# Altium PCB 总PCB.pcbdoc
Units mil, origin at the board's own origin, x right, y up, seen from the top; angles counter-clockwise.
Board outline 1771.65 x 3543.31 mil, 2 copper layers (Top Layer, Bottom Layer), stack 62.205 mil thick; 113 components, 79 nets, 415 pads, 177 vias.
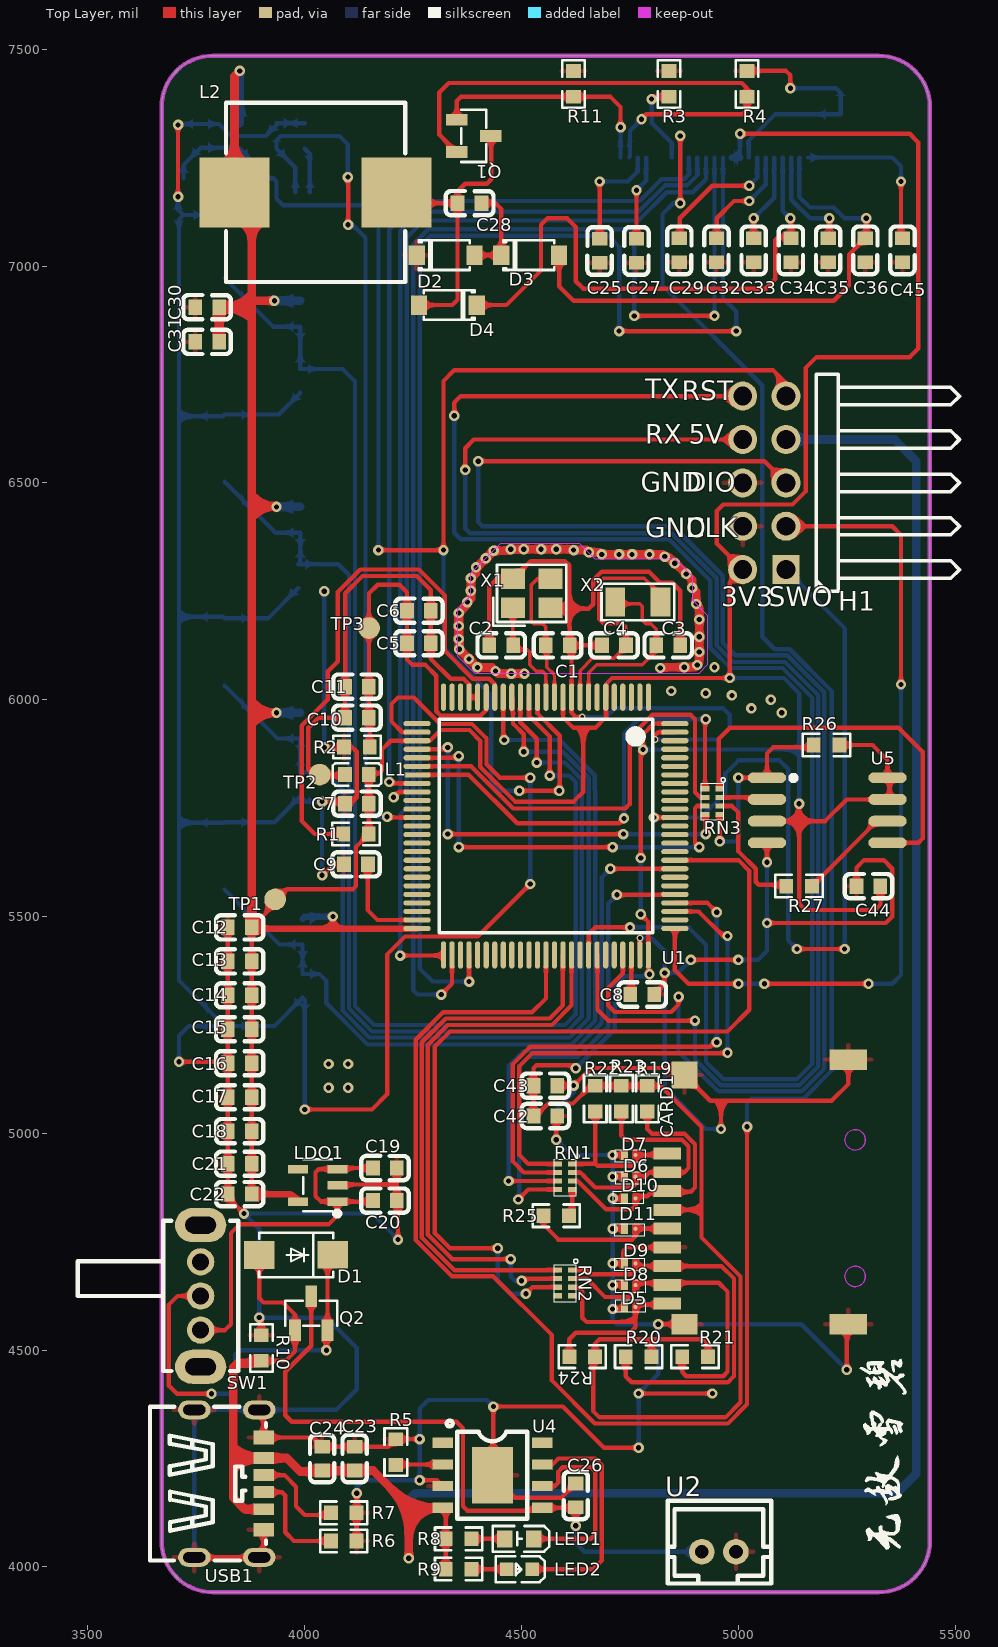
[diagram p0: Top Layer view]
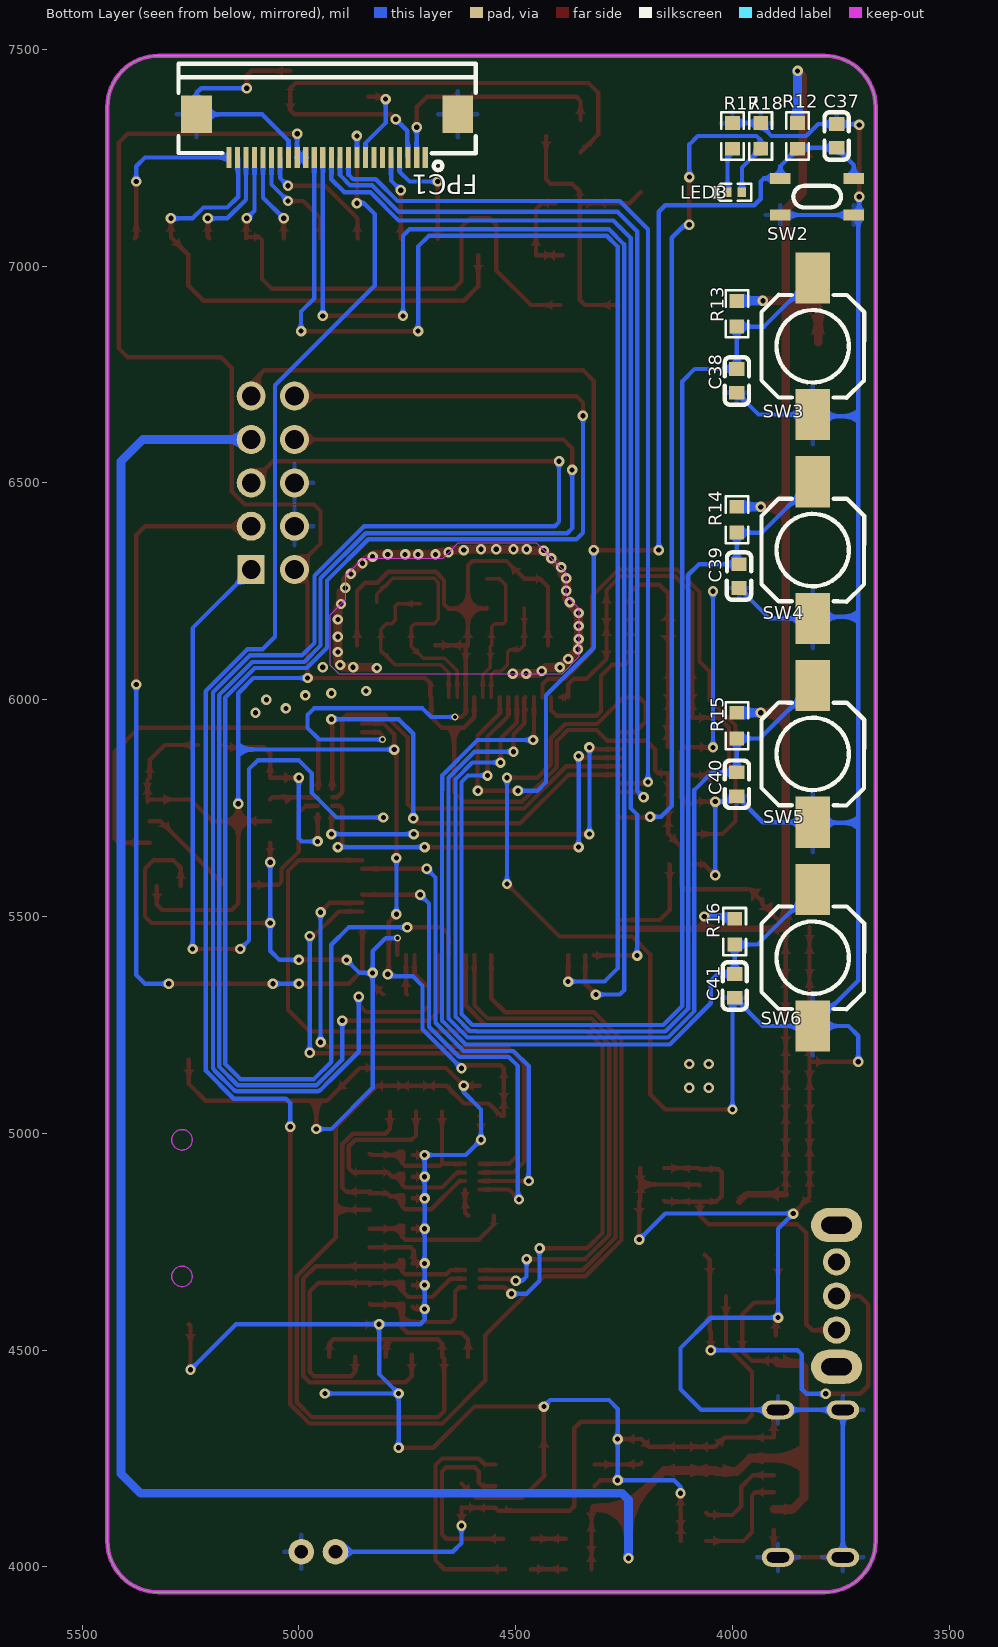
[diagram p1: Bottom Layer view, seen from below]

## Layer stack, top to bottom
Top Solder Mask Layer: solder mask 0.394, Dk 3.3
Top Layer: signal copper 1.378
Dielectric1: surface 59.449, FR4, Dk 4.5
Bottom Layer: signal copper 1.378
Bottom Solder Mask Layer: solder mask 0.394, Dk 3.3

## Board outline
3788.11,7485 5323.54,7485 cw(c5323.54,7366.89) 5441.65,7366.89 5441.65,4059.8 cw(c5323.54,4059.8) 5323.54,3941.69 3788.11,3941.69 cw(c3788.11,4059.8) 3670,4059.8 3670,7366.89 cw(c3788.11,7366.89)

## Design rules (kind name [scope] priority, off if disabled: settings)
BoardOutlineClearance copperThickness1oz [All] p0: genericclearance=10 ignorepadtopadclearanceinfootprint=FALSE except(0: Arc-SplitContinuation Track-SplitContinuation SMDPad-SplitContinuation THPad-SplitContinuation Via-SplitContinuation Fill-SplitContinuation Poly-SplitContinuation Region-SplitContinuation Text-SplitContinuation)
BoardOutlineClearance copperThickness2oz [All] p0: genericclearance=10 ignorepadtopadclearanceinfootprint=FALSE except(0: Arc-SplitContinuation Track-SplitContinuation SMDPad-SplitContinuation THPad-SplitContinuation Via-SplitContinuation Fill-SplitContinuation Poly-SplitContinuation Region-SplitContinuation Text-SplitContinuation)
BoardOutlineClearance copperThicknessInner0.5oz [All] p0: genericclearance=10 ignorepadtopadclearanceinfootprint=FALSE except(0: Arc-SplitContinuation Track-SplitContinuation SMDPad-SplitContinuation THPad-SplitContinuation Via-SplitContinuation Fill-SplitContinuation Poly-SplitContinuation Region-SplitContinuation Text-SplitContinuation)
BoardOutlineClearance otherClearance [All] p0: genericclearance=10 ignorepadtopadclearanceinfootprint=FALSE except(0: Arc-SplitContinuation Track-SplitContinuation SMDPad-SplitContinuation THPad-SplitContinuation Via-SplitContinuation Fill-SplitContinuation Poly-SplitContinuation Region-SplitContinuation Text-SplitContinuation)
Clearance copperThickness1oz [All] p1: gap=7 ignorepadtopadclearanceinfootprint=FALSE
Clearance copperThickness2oz [All] p1: gap=7 ignorepadtopadclearanceinfootprint=FALSE
Clearance copperThicknessInner0.5oz [All] p1: gap=7 ignorepadtopadclearanceinfootprint=FALSE
Clearance otherClearance [All] p1: gap=7 ignorepadtopadclearanceinfootprint=FALSE
DiffPairsRouting differentialPair [All] p1: maxuncoupledlength=10 minlimit=5.9843 maxlimit=Infinity mostfreqgap=5.9843 toplayer_minwidth=5 toplayer_prefwidth=10 toplayer_maxwidth=100 bottomlayer_minwidth=5 bottomlayer_prefwidth=10 bottomlayer_maxwidth=100
PasteMaskExpansion pasteMaskExpansion [All] p1: expansion=0
PlaneConnect innerPlane [All] p1: planeconnectstyle=Relief reliefexpansion=20 reliefentries=4 reliefconductorwidth=10 reliefairgap=10
PolygonConnect copperRegion [All] p1: connectstyle=Relief reliefentries=4 reliefconductorwidth=10 polygonreliefangle="90 Angle" airgapwidth=10
RoutingVias viaSize [All] p1: viastyle="Through Hole" holewidth=12.0078 minholewidth=7.874 maxholewidth=248.0314 width=12.0078 minwidth=7.874 maxwidth=248.0314
SolderMaskExpansion solderMaskExpansion [IsVia] p1: useseparateexpansions=TRUE expansion=-1000 expansionbottom=-1000
SolderMaskExpansion solderMaskExpansion [All] p2: useseparateexpansions=TRUE expansion=2.0079 expansionbottom=2.0079
Width copperThickness1oz [All] p1: maxlimit=100 minlimit=4 preferedwidth=10
Width copperThickness2oz [All] p1: maxlimit=100 minlimit=8 preferedwidth=10
Width copperThickness0.5oz [All] p1: maxlimit=100 minlimit=4 preferedwidth=10

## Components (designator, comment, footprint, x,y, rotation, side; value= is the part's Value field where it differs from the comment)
C1 "20pF" C0603#1 4583.25,6125.21 r180 top
C2 "20pF" C0603#1 4453.25,6125.21 r0 top
C3 "12pF" C0603#1 4838.25,6125.21 r180 top
C4 "12pF" C0603#1 4713.25,6125.21 r0 top
C5 "1uF" C0603#1 4263.25,6130.21 r0 top
C6 "100nF" C0603#1 4263.25,6205.21 r180 top
C7 "100nF" C0603#1 4120.44,5760.21 r180 top
C8 "2.2uF" C0603#1 4778.25,5320.21 r180 top
C9 "2.2uF" C0603#1 4118.25,5620.21 r0 top
C10 "1uF" C0603#1 4120.44,5958.57 r0 top
C11 "100nF" C0603#1 4120.44,6030.21 r180 top
C12 "10uF" C0603#1 3850,5475 r0 top
C13 "100nF" C0603#1 3850,5396.67 r0 top
C14 "100nF" C0603#1 3850,5318.33 r0 top
C15 "100nF" C0603#1 3850,5240 r0 top
C16 "100nF" C0603#1 3850,5161.67 r0 top
C17 "100nF" C0603#1 3850,5083.33 r0 top
C18 "100nF" C0603#1 3850,5005 r0 top
C19 "100nF" C0603#1 4185,4920 r180 top
C20 "1uF" C0603#1 4185,4845 r180 top
C21 "1uF" C0603#1 3850,4930 r0 top
C22 "100nF" C0603#1 3850,4860 r0 top
C23 "22uF" C0603#1 4115,4250 r270 top
C24 "100nF" C0603#1 4040,4250 r90 top
C25 "100nF" C0603#2 4680,7035 r90 top
C26 "10uF" C0603#1 4625,4165 r270 top
C27 "100nF" C0603#2 4765,7035 r90 top
C28 "100nF" C0603#2 4380,7145 r180 top
C29 "100nF" C0603#2 4863.79,7036.42 r90 top
C30 "100nF" C0603#2 3775,6905 r0 top
C31 "100nF" C0603#2 3775,6825 r0 top
C32 "100nF" C0603#2 4949.6,7036.42 r90 top
C33 "100nF" C0603#2 5035.4,7036.42 r90 top
C34 "100nF" C0603#2 5121.21,7036.42 r90 top
C35 "100nF" C0603#2 5207.02,7036.42 r90 top
C36 "100nF" C0603#2 5292.82,7036.42 r90 top
C37 "100nF" C0603#1 3760,7300 r90 bottom
C38 "100nF" C0603#1 3990,6735 r90 bottom
C39 "100nF" C0603#1 3985,6285 r90 bottom
C40 "100nF" C0603#1 3990,5805 r90 bottom
C41 "100nF" C0603#1 3995,5340 r90 bottom
C42 "10uF" C0603#1 4555,5040 r0 top
C43 "100nF" C0603#1 4555,5110 r180 top
C44 "100nF" C0603#1 5300,5570 r180 top
C45 "100nF" C0603#2 5378.63,7036.42 r90 top
CARD1 "XKTF-015-G" TF-SMD_XKTF-015-N 5045,4865 r90 top
D1 "SS34" SMA_L4.3-W2.6-LS5.0-FD 3980,4720 r0 top
D2 "B5819W" SOD-123_L2.8-W1.8-LS3.7-RD 4325,7025 r0 top
D3 "B5819W" SOD-123_L2.8-W1.8-LS3.7-RD 4520,7025 r0 top
D4 "B5819W" SOD-123_L2.8-W1.8-LS3.7-RD 4330,6910 r180 top
D5 "LESD8D5.0CAT5G" DFN-2L_L1.0-W0.6-P0.65-BI 4750,4600 r180 top
D6 "LESD8D5.0CAT5G" DFN-2L_L1.0-W0.6-P0.65-BI 4750,4900 r180 top
D7 "LESD8D5.0CAT5G" DFN-2L_L1.0-W0.6-P0.65-BI 4750,4950 r180 top
D8 "LESD8D5.0CAT5G" DFN-2L_L1.0-W0.6-P0.65-BI 4750,4650 r180 top
D9 "LESD8D5.0CAT5G" DFN-2L_L1.0-W0.6-P0.65-BI 4750,4700 r180 top
D10 "LESD8D5.0CAT5G" DFN-2L_L1.0-W0.6-P0.65-BI 4750,4850 r180 top
D11 "LESD8D5.0CAT5G" DFN-2L_L1.0-W0.6-P0.65-BI 4750,4780 r180 top
FPC1 "0.5K-DX-24PWB" FPC-SMD_24P-P0.50_HDGC_0.5K-DX-24PWBG 4935,7300 r0 bottom
H1 "PH2.54-07-05PWS" HDR-TH_10P-P2.54-H-M-R2-C5-S2.54-W12.9 5060,6500 r90 top
L1 "GZ1608D601TF" L0603 4120.44,5827.49 r180 top
L2 "68uH" IND-SMD_L11.5-W10.5_SRG1040 4025,7170 r0 top
LDO1 "ME6211C33M5G-N" SOT-23-5_L3.0-W1.7-P0.95-LS2.8-BL 4030,4880 r90 top
LED1 "GL0603UR01" LED0603-FD 4495,4065 r0 top
LED2 "MHT192DUGCT" LED0603-RD 4495,3995 r180 top
LED3 "NCD0402G1" LED0402-RD 3995,7170 r180 bottom
Q1 "SI2300" SOT-23-3_L2.9-W1.3-P1.90-LS2.4-BR#1 4390,7300 r180 top
Q2 "DMP1045U-7" SOT-23-3_L2.9-W1.3-P1.90-LS2.4-BR#2 4015,4585 r270 top
R1 "0Ω" R0603 4118.25,5690.21 r180 top
R2 "0Ω" R0603 4120.44,5890.87 r0 top
R3 "10K" R0603 4840,7420 r270 top
R4 "10K" R0603 5020,7420 r90 top
R5 "1.2kΩ" R0603 4210,4265 r270 top
R6 "5.1kΩ" R0603 4090,4060 r0 top
R7 "5.1kΩ" R0603 4090,4125 r0 top
R8 "1kΩ" R0603 4355,4065 r0 top
R9 "1kΩ" R0603 4355,3995 r0 top
R10 "10kΩ" R0603 3900,4505 r90 top
R11 "10K" R0603 4620,7420 r270 top
R12 "10kΩ" R0603 3850,7300 r90 bottom
R13 "10K" R0603 3990,6890 r90 bottom
R14 "10K" R0603 3990,6415 r90 bottom
R15 "10K" R0603 3990,5940 r90 bottom
R16 "10K" R0603 3995,5465 r90 bottom
R17 "2kΩ" R0603 4000,7300 r90 bottom
R18 "10kΩ" R0603 3935,7300 r270 bottom
R19 "47kΩ" R0603 4790,5080 r90 top
R20 "47kΩ" R0603 4770,4485 r0 top
R21 "47kΩ" R0603 4900,4485 r0 top
R22 "47kΩ" R0603 4670,5080 r90 top
R23 "47kΩ" R0603 4730,5080 r90 top
R24 "47kΩ" R0603 4640,4485 r0 top
R25 "22Ω" R0603 4580,4810 r180 top
R26 "10kΩ" R0603 5203.42,5895.5 r0 top
R27 "22Ω" R0603 5140,5570 r180 top
RN1 "0Ω" RES-ARRAY-SMD_0402-8P-L2.0-W1.0-BL 4600,4900 r270 top
RN2 "0Ω" RES-ARRAY-SMD_0402-8P-L2.0-W1.0-BL 4600,4655 r270 top
RN3 "0Ω" RES-ARRAY-SMD_0402-8P-L2.0-W1.0-BL 4940,5765 r270 top
SW1 "SK12D07VG5" SW-TH_SK12D07VG5-1 3760,4625 r270 top
SW2 "TSA017A2540A03" SW-SMD_4P-L4.2-W3.4-P2.15-LS5.2 3805,7160 r0 bottom
SW3 "TS-1817A-5026" SW-SMD_L6.0-W6.0-LS8.0 3815,6815 r90 bottom
SW4 "TS-1817A-5026" SW-SMD_L6.0-W6.0-LS8.0 3815,6345 r90 bottom
SW5 "TS-1817A-5026" SW-SMD_L6.0-W6.0-LS8.0 3815,5875 r90 bottom
SW6 "TS-1817A-5026" SW-SMD_L6.0-W6.0-LS8.0 3815,5405 r90 bottom
TP1 "" Test-Point-0.5mm 3931.7,5539.65 r0 top
TP2 "" Test-Point-0.5mm 4034.65,5827.28 r0 top
TP3 "" Test-Point-0.5mm 4148.25,6165.21 r0 top
U1 "" LQFP-100_L14.0-W14.0-P0.50-LS16.0-BL 4556.28,5708.56 r180 top locked
U2 "WAFER-PH2.0-2PZZ" CONN-TH_2P-P2.00_HC-PH-2A-M 4955,4035 r0 top
U4 "TC4056A." ESOP-8_L4.9-W3.9-P1.27-LS6.0-BL-EP 4432.73,4211.49 r270 top
U5 "GD25Q32CSIGR" SOIC-8_L5.3-W5.3-P1.27-LS8.0-BL 5205,5745 r270 top
USB1 "TYPE-C 6P" TYPE-C-SMD_TYPE-C-6P_1 3825.26,4192.2 r270 top
X1 "8MHz" CRYSTAL-SMD_4P-L3.2-W2.5-BL 4523.25,6245.21 r0 top
X2 "32.768kHz" OSC-SMD_2P-L3.2-W1.5 4768.25,6225.21 r0 top

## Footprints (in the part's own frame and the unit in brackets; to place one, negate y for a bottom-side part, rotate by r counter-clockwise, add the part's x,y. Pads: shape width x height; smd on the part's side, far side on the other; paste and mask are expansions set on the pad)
C0603#1 [mm]
  rect 0.8x0.9 smd: 1(-0.7,0) 2(0.7,0)
  silkscreen extent -1.39,-0.71 1.39,0.71
C0603#2 [mm]
  rect 0.8x0.9 smd paste+0 mask+0.051: 1(-0.7,0) 2(0.7,0)
  silkscreen extent -1.41,-0.71 1.39,0.72
CONN-TH_2P-P2.00_HC-PH-2A-M [mm]
  round 1.5 hole 0.8 paste+0 mask+0.05: 1(-1,0) 2(1,0)
  silkscreen extent -3,-1.86 3.06,3
CRYSTAL-SMD_4P-L3.2-W2.5-BL [mm]
  rect 1.4x1.2 smd: 1(-1.1,-0.85) 2(1.1,-0.85) 3(1.1,0.85) 4(-1.1,0.85)
  silkscreen extent -2.26,-1.91 2.03,1.68
DFN-2L_L1.0-W0.6-P0.65-BI [mm]
  round 0.246 smd: 1(-0.325,0)
  rect 0.4x0.6 smd: 2(0.325,0)
  Top Layer region: -0.53,0.3 -0.53,-0.3 -0.2,-0.3 -0.12,-0.2 -0.12,0.3
ESOP-8_L4.9-W3.9-P1.27-LS6.0-BL-EP [mm]
  rect 0.6x1.2 smd: 1(-1.905,-2.908) 2(-0.635,-2.908) 3(0.635,-2.908) 4(1.905,-2.908) 5(1.905,2.908) 6(0.635,2.908) 7(-0.635,2.908) 8(-1.905,2.908)
  rect 3.3x2.4 smd: 9(0,0)
  silkscreen extent -3.2,-2.67 2.55,2.05
FPC-SMD_24P-P0.50_HDGC_0.5K-DX-24PWBG [mm]
  rect 0.3x1.25 smd paste+0 mask+0.05: 1(-5.75,1.262) 2(-5.25,1.262) 3(-4.75,1.262) 4(-4.25,1.263) 5(-3.75,1.262) 6(-3.25,1.262) 7(-2.75,1.263) 8(-2.25,1.263) 9(-1.75,1.263) 10(-1.25,1.263) 11(-0.75,1.263) 12(-0.25,1.263) 13(0.25,1.263) 14(0.75,1.263) 15(1.25,1.263) 16(1.75,1.263) 17(2.25,1.263) 18(2.75,1.263) 19(3.25,1.263) 20(3.75,1.263) 21(4.25,1.263) 22(4.75,1.263) 23(5.25,1.263) 24(5.75,1.263)
  rect 1.8x2.2 smd paste+0 mask+0.05: 25(7.65,-1.263) 26(-7.65,-1.263)
  silkscreen extent -8.7,-4.24 8.7,2
HDR-TH_10P-P2.54-H-M-R2-C5-S2.54-W12.9 [mm]
  rect 1.7x1.575 hole 1.1: 1(-5.08,-1.27)
  round 1.7 hole 1.1: 2(-5.08,1.27) 3(-2.54,-1.27) 4(-2.54,1.27) 5(0,-1.27) 6(0,1.27) 7(2.54,-1.27) 8(2.54,1.27) 9(5.08,-1.27) 10(5.08,1.27)
  silkscreen extent -6.35,-11.43 6.35,-3.05
IND-SMD_L11.5-W10.5_SRG1040 [mm]
  rect 4.1x4.1 smd: 1(-4.75,0) 2(4.75,0)
  silkscreen extent -5.25,-5.25 5.25,5.25
L0603 [mm]
  rect 0.8x0.864 smd paste-100 mask+0.051: 1(-0.7,0) 2(0.7,0)
  silkscreen extent -1.42,-0.65 1.42,0.65
LED0402-RD [mm]
  rect 0.5x0.54 smd: 1(-0.425,0) 2(0.425,0)
  silkscreen extent -1.28,-0.5 0.98,0.5
LED0603-FD [mm]
  rect 0.9x1 smd: 1(-0.85,0) 2(0.85,0)
  silkscreen extent -1.55,-0.75 1.75,0.75
LED0603-RD [mm]
  rect 0.8x0.8 smd: 1(-0.749,0) 2(0.749,0)
  silkscreen extent -1.49,-0.75 1.39,0.76
LQFP-100_L14.0-W14.0-P0.50-LS16.0-BL [mm]
  oval 0.3x1.6 smd paste-100 mask+0.051: 1(-6,-7.55) 2(-5.5,-7.55) 3(-5,-7.55) 4(-4.5,-7.55) 5(-4,-7.55) 6(-3.5,-7.55) 7(-3,-7.55) 8(-2.5,-7.55) 9(-2,-7.55) 10(-1.5,-7.55) 11(-1,-7.55) 12(-0.5,-7.55) 13(0,-7.55) 14(0.5,-7.55) 15(1,-7.55) 16(1.5,-7.55) 17(2,-7.55) 18(2.5,-7.55) 19(3,-7.55) 20(3.5,-7.55) 21(4,-7.55) 22(4.5,-7.55) 23(5,-7.55) 24(5.5,-7.55) 25(6,-7.55) 51(6,7.55) 52(5.5,7.55) 53(5,7.55) 54(4.5,7.55) 55(4,7.55) 56(3.5,7.55) 57(3,7.55) 58(2.5,7.55) 59(2,7.55) 60(1.5,7.55) 61(1,7.55) 62(0.5,7.55) 63(0,7.55) 64(-0.5,7.55) 65(-1,7.55) 66(-1.5,7.55) 67(-2,7.55) 68(-2.5,7.55) 69(-3,7.55) 70(-3.5,7.55) 71(-4,7.55) 72(-4.5,7.55) 73(-5,7.55) 74(-5.5,7.55) 75(-6,7.55)
  oval 1.6x0.3 smd paste-100 mask+0.051: 26(7.55,-6) 27(7.55,-5.5) 28(7.55,-5) 29(7.55,-4.5) 30(7.55,-4) 31(7.55,-3.5) 32(7.55,-3) 33(7.55,-2.5) 34(7.55,-2) 35(7.55,-1.5) 36(7.55,-1) 37(7.55,-0.5) 38(7.55,0) 39(7.55,0.5) 40(7.55,1) 41(7.55,1.5) 42(7.55,2) 43(7.55,2.5) 44(7.55,3) 45(7.55,3.5) 46(7.55,4) 47(7.55,4.5) 48(7.55,5) 49(7.55,5.5) 50(7.55,6) 76(-7.55,6) 77(-7.55,5.5) 78(-7.55,5) 79(-7.55,4.5) 80(-7.55,4) 81(-7.55,3.5) 82(-7.55,3) 83(-7.55,2.5) 84(-7.55,2) 85(-7.55,1.5) 86(-7.55,1) 87(-7.55,0.5) 88(-7.55,0) 89(-7.55,-0.5) 90(-7.55,-1) 91(-7.55,-1.5) 92(-7.55,-2) 93(-7.55,-2.5) 94(-7.55,-3) 95(-7.55,-3.5) 96(-7.55,-4) 97(-7.55,-4.5) 98(-7.55,-5) 99(-7.55,-5.5) 100(-7.55,-6)
  silkscreen extent -6.25,-6.25 6.25,6.25
OSC-SMD_2P-L3.2-W1.5 [mm]
  rect 1.15x1.7 smd: 1(-1.325,0) 2(1.325,0)
  silkscreen extent -2.39,-1.08 2.13,1.37
R0603 [mil]
  rect 31.75x34.02 smd paste-3937.01 mask+2: 1(-29.66,0) 2(29.66,0)
  silkscreen extent -55,-26 55,26
RES-ARRAY-SMD_0402-8P-L2.0-W1.0-BL [mm]
  rect 0.3x0.505 smd: 1(-0.75,0.427) 2(-0.25,0.427) 3(0.25,0.427) 4(0.75,0.427) 5(0.75,-0.427) 6(0.25,-0.427) 7(-0.25,-0.427) 8(-0.75,-0.427)
  silkscreen extent -1.31,0.59 -1.08,0.83
SMA_L4.3-W2.6-LS5.0-FD [mm]
  rect 1.8x1.62 smd: 1(-2.15,-0.009) 2(2.15,0.009)
  silkscreen extent -2.17,-1.32 2.19,1.29
SOD-123_L2.8-W1.8-LS3.7-RD [mm]
  rect 0.95x1.15 smd paste+0 mask+0.051: 1(-1.692,0) 2(1.692,0)
  silkscreen extent -1.58,-0.87 1.41,0.87
SOIC-8_L5.3-W5.3-P1.27-LS8.0-BL [mm]
  oval 0.63x2.25 smd: 1(-1.905,-3.53) 2(-0.635,-3.53) 3(0.635,-3.53) 4(1.905,-3.53) 5(1.905,3.53) 6(0.635,3.53) 7(-0.635,3.53) 8(-1.905,3.53)
  silkscreen extent -2.04,-2.13 -1.74,-1.83
SOT-23-3_L2.9-W1.3-P1.90-LS2.4-BR#1 [mm]
  rect 1.25x0.7 smd paste+0 mask+0.051: 1(1,-0.95) 2(1,0.95) 3(-1,0)
  silkscreen extent -0.73,-1.53 0.73,1.53
SOT-23-3_L2.9-W1.3-P1.90-LS2.4-BR#2 [mm]
  rect 1.25x0.7 smd: 1(1,-0.95) 2(1,0.95) 3(-1,0)
  silkscreen extent -0.73,-1.53 0.73,1.53
SOT-23-5_L3.0-W1.7-P0.95-LS2.8-BL [mm]
  rect 0.49x1.157 smd: 1(-0.95,-1.154) 2(0,-1.154) 3(0.95,-1.154)
  rect 0.49x1.175 smd: 4(0.95,1.154) 5(-0.95,1.154)
  silkscreen extent -1.8,-1.29 1.53,0.85
SW-SMD_4P-L4.2-W3.4-P2.15-LS5.2 [mm]
  rect 1.2x0.65 smd: 1(-2.15,1.075) 2(2.15,1.075) 3(-2.15,-1.075) 4(2.15,-1.075)
  silkscreen extent -1.4,-0.63 1.39,0.64
SW-SMD_L6.0-W6.0-LS8.0 [mm]
  rect 3x2 smd: 1(-4,0) 2(4,0)
  silkscreen extent -3.02,-3.02 3.01,3
SW-TH_SK12D07VG5-1 [mm]
  round 1.6 hole 1: 1(-2,0) 2(0,0) 3(2,0)
  oval 2x3 hole 1 slot 1.8 at 90 deg: 4(4.15,0) 5(-4.15,0)
  silkscreen extent -4.4,-7.2 4.4,2.2
Test-Point-0.5mm [mil]
  round 50 smd: 1(0,0)
TF-SMD_XKTF-015-N [mm]
  rect 0.7x1.6 smd: 1(2.25,5.3) 2(1.15,5.3) 3(0.05,5.3) 4(-1.05,5.3) 5(-2.15,5.3) 6(-3.25,5.3) 7(-4.35,5.3) 8(-5.45,5.3) 9(-6.55,5.3)
  rect 1.2x1.5 smd: 10(-7.75,4.3)
  rect 1.2x2.2 smd: 11(-7.75,-5.3) 13(7.75,-5.3)
  rect 1.6x1.5 smd: 12(6.85,4.3)
  Board Outline Layer circle w0.003: c3.05,-5.7 r0.6
  Board Outline Layer circle w0.003: c-4.95,-5.7 r0.6
  Board Outline Layer region: 3.05,-6.3 2.79,-6.241 2.581,-6.074 2.465,-5.834 2.465,-5.567 2.581,-5.326 2.79,-5.159 3.05,-5.1 3.05,-5.1 3.31,-5.159 3.519,-5.326 3.635,-5.567 3.635,-5.834 3.519,-6.074 3.31,-6.241 3.05,-6.3
  Board Outline Layer region: 3.05,-6.3 2.79,-6.241 2.581,-6.074 2.465,-5.834 2.465,-5.567 2.581,-5.326 2.79,-5.159 3.05,-5.1 3.05,-5.1 3.31,-5.159 3.519,-5.326 3.635,-5.567 3.635,-5.834 3.519,-6.074 3.31,-6.241 3.05,-6.3
  Board Outline Layer region: -4.95,-6.3 -5.21,-6.241 -5.419,-6.074 -5.535,-5.834 -5.535,-5.567 -5.419,-5.326 -5.21,-5.159 -4.95,-5.1 -4.95,-5.1 -4.69,-5.159 -4.481,-5.326 -4.365,-5.567 -4.365,-5.834 -4.481,-6.074 -4.69,-6.241 -4.95,-6.3
  Board Outline Layer region: -4.95,-6.3 -5.21,-6.241 -5.419,-6.074 -5.535,-5.834 -5.535,-5.567 -5.419,-5.326 -5.21,-5.159 -4.95,-5.1 -4.95,-5.1 -4.69,-5.159 -4.481,-5.326 -4.365,-5.567 -4.365,-5.834 -4.481,-6.074 -4.69,-6.241 -4.95,-6.3
TYPE-C-SMD_TYPE-C-6P_1 [mm]
  oval 1.1x1.9 hole 0.6 slot 1.3 at 90 deg: 7(-4.32,1.775) 7(-4.32,-2.025) 7(4.32,1.775) 7(4.32,-2.025)
  rect 0.7x1.2 smd paste-100 mask+0.051: A5(-0.5,2.025) A9(1.5,2.025) B5(0.5,2.025) B9(-1.5,2.025)
  rect 0.8x1.2 smd paste-100 mask+0.051: A12(2.7,2.025) B12(-2.7,2.025)
  silkscreen extent -4.5,-4.63 4.5,2.18

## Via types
v1: diameter 24.02, hole 12.01, Top Layer to Bottom Layer, 174 vias
v2: diameter 16, hole 9, Top Layer to Bottom Layer, 3 vias

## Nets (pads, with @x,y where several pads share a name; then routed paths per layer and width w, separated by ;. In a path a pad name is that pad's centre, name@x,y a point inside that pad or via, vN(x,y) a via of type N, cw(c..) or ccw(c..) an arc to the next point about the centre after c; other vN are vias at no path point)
$1I7\$2N9: C9.2 U1.49 | length 229.1
  Top Layer w10: C9.2 4145,5619.41 4145,5515 4167.98,5492.02 U1.49
$1I7\$2N12: R1.2 U1.19 | length 1268.2
  Top Layer w10: R1.2 4023.25,5690.21 3993.25,5720.21 3993.25,5940.21 4053.25,6000.21 4053.25,6065.21 4076.24,6088.2 4076.24,6248.2 4128.25,6300.21 4263.25,6300.21 4323.25,6240.21 4323.25,6111.99 4386.96,6048.28 4425.47,6048.28 4438.25,6035.51 4438.25,6005.88 U1.19
$1I7\$2N16: C8.2 U1.73 | length 92.1
  Top Layer w10: C8.2 4753.13,5322.66 U1.73
$1I7\BOOT0: U1.94
$1I7\OSC32_IN: C3.2 U1.8 X2.1 | length 416.2
  Top Layer w8: U1.8 4654.71,6061.68 4673.25,6080.21 4778.25,6080.21 4810.69,6112.65 C3.2 4810.69,6162.77 4798.25,6175.21 4786.25,6175.21 4778.25,6183.21 4778.25,6215.21 4772.59,6220.87 X2.1@4720.42,6220.87
$1I7\OSC32_OUT: C4.2 U1.9 X2.2 | length 569.3
  Top Layer w8: U1.9 4635.02,6066.99 4663.25,6095.21 4713.25,6095.21 4740.81,6122.77 C4.2 4740.81,6167.65 4733.25,6175.21 4688.25,6175.21 4678.25,6185.21 4678.25,6270.21 4688.25,6280.21 4783.25,6280.21 4820.42,6243.04 X2.2
$1I7\OSC_IN: C1.2 U1.12 X1.3 | length 342.4
  Top Layer w8: X1.3 4536.71,6278.68 4522.59,6264.56 4522.59,6180.87 4528.25,6175.21 4548.25,6175.21 4555.69,6167.77 C1.2 4558.25,6122.65 4558.25,6075.21 4575.96,6057.5 U1.12
$1I7\OSC_OUT: C2.2 U1.13 X1.1 | length 259.1
  Top Layer w8: X1.1 4479.94,6126.08 C2.2 4490.81,6115.21 4513.25,6115.21 4518.9,6109.56 4518.9,6080.21 4533.9,6065.21 4548.25,6065.21 4556.28,6057.18 U1.13
$1I7\PA9: H1.10 U1.68 | length 3777.1
  Top Layer w10: v1(4345,6655) 4345,6685 4360,6700 H1.10 ; U1.68 4655,5411.61 4655,5460 4670,5475 v1(4750,5475)
  Bottom Layer w10: v1(4345,6655) 4345,6385 4360,6370 4840,6370 4935,6275 4935,6120 4982.01,6072.99 5101.83,6072.99 5170,6004.82 5170,5160 5135,5125 4965,5125 4925.29,5164.71 4925.29,5435 4885.29,5475 v1(4750,5475)
$1I7\PA10: H1.8 U1.69 | length 3532.3
  Top Layer w10: v1(4370,6530) 4370,6580 4390,6600 H1.8 ; U1.69 4675,5410.71 4675,5285 4700,5260 v1(4900,5260)
  Bottom Layer w10: v1(4370,6530) 4370,6395 4380.98,6384.02 4845.98,6384.02 4950,6280 4950,6124.82 4987.81,6087.01 5107.63,6087.01 5174.64,6020 5175,6020 5182.07,6012.93 5182.07,6012.57 5184.02,6010.63 5184.02,5154.19 5140.81,5110.98 4959.19,5110.98 4920.18,5150 4920,5150 4900,5170 v1(4900,5260)
$1I7\SWCLK: H1.3 U1.76 | length 1926.9
  Top Layer w10: U1.76 4853.52,5376.48 4885,5345 v1(5000,5345) ; v1(5060,5345) v1(5300,5345) ; H1.3 5355,6400 5375,6380 v1(5375,6035)
  Bottom Layer w10: v1(5000,5345) v1(5060,5345) ; v1(5300,5345) 5355,5345 5375,5365 v1(5375,6035)
$1I7\SWDIO: H1.5 U1.72 | length 3634.6
  Top Layer w10: v1(4400,6550) 5060,6550 H1.5 ; U1.72 4733.45,5368.45 4700,5335 4700,5295 4715,5280 4845,5280 4862.07,5297.07 v1(4862.07,5315)
  Bottom Layer w10: v1(4400,6550) 4400,6410 4410,6400 4850,6400 4964.02,6285.98 4964.02,6130.98 4992.74,6102.26 5112.74,6102.26 5198.03,6016.97 5198.03,5154.19 cw(c5184.02,5154.19) 5193.93,5144.28 5150.72,5101.07 cw(c5140.81,5110.98) 5140.81,5096.97 4959.19,5096.97 cw(c4959.19,5110.98) 4949.28,5101.07 4930.36,5120 4930,5120 4862.07,5187.93 v1(4862.07,5315)
$1I7\SWO: H1.1 U1.89 | length 1906.9
  Top Layer w10: v1(4805,5728.24) U1.89 ; v1(5135,5425) v1@5240,5425
  Bottom Layer w10: v1(4805,5728.24) 4913.24,5728.24 4970,5785 4970,5830 5000,5860 5095,5860 5115,5840 5115,5445 v1(5135,5425) ; H1.1 5245,6165 v1(5245,5425)
$1I7\VDDA: C5.2 C6.1 C10.1 C11.2 L1.2 TP2.1 U1.21 U1.22 | length 1116.1
  Top Layer w8: U1.22 U1.21
  Top Layer w10: L1.2 4090.61,5825.21 4023.25,5825.21 4008.25,5840.21 4008.25,5935.21 4031.6,5958.57 C10.1 C11.2 4093.25,6030.58 4093.25,6245.21 4133.25,6285.21 4258.25,6285.21 4290.81,6252.65 C6.1 C5.2 4290.81,6094.1 4336.63,6048.28 4366.42,6048.28 4379.11,6035.6 U1.22
$1I10\$1N26: R27.1 U5.6 | length 236.5
  Top Layer w10: R27.1 5319.66,5720 U5.6
$1I10\$1N34: CARD1.5 D11.1 R25.2 | length 341.3
  Top Layer w10: R25.2 4550.34,4789.66 4585,4755 4755,4755 4762.8,4762.8 D11.1 4763.15,4780.35 CARD1.5
$1I10\_SD_CARD_DET: CARD1.9 D5.1 R24.1 RN2.3 | length 545.7
  Top Layer w10: R24.1 4610,4485.34 4610,4525 4625,4540 4750,4540 4762.8,4552.8 4762.8,4561.1 ; RN2.3 4629.84,4645.16 4640,4635 4640,4575 4650,4565 4758.9,4565 4762.8,4561.1 ; CARD1.9 4834.22,4605 4765,4605 4765,4602.2 D5.1 4762.8,4561.1
$1I10\_SDIO_CLK: R25.1 RN1.4 | length 63.4
  Top Layer w10: R25.1 4616.83,4817.17 RN1.4
$1I10\_SDIO_CMD: CARD1.3 D10.1 R19.1 RN1.3 | length 605.2
  Top Layer w10: RN1.3 4629.84,4890.16 4695,4825 4755,4825 4762.8,4832.8 D10.1 4767.8,4855 4790,4855 4796.97,4861.97 CARD1.3@4836.34,4861.97 ; R19.1 4790,5010 4800.98,4999.02 4875.81,4999.02 4900,4974.82 4900,4875 4890,4865 4838.31,4865 CARD1.3
$1I10\_SDIO_D0: CARD1.7 D9.1 R20.1 RN2.1 | length 942.8
  Top Layer w10: RN2.1 4617.3,4685 4649.82,4685 4659.82,4675 4755,4675 4762.8,4682.8 D9.1 ; R20.1@4740.34,4490 4740,4489.66 4740,4440 4754.02,4425.98 4975.81,4425.98 4990,4440.18 4990,4665 4961.26,4693.74 CARD1.7 4766.53,4693.74
$1I10\_SDIO_D1: CARD1.8 D8.1 R21.1 RN2.2 | length 738
  Top Layer w10: RN2.2 4650.16,4664.84 4692.5,4622.5 4724.49,4622.5 4724.78,4622.79 4747.79,4622.79 4762.8,4637.8 D8.1 ; 4762.8,4655 4831.77,4655 CARD1.8 ; CARD1.8@4836.34,4655.43 4954.57,4655.43 4975,4635 4975,4450 4965,4440 4880,4440 4870,4450 4870,4484.66 R21.1
$1I10\_SDIO_D2: CARD1.1 D7.1 R22.1 RN1.1 | length 364.3
  Top Layer w10: RN1.1 4670.47,4929.53 ; R22.1 4670,4930 4670.47,4929.53 ; CARD1.1 4832.76,4950 D7.1 4762.8,4932.8 4755,4925 4675,4925 4670.47,4929.53
$1I10\_SDIO_D3: CARD1.2 D6.1 R23.1 RN1.2 | length 582.6
  Top Layer w10: RN1.2 4635.69,4909.84 4645.82,4899.71 4645.82,4899.18 4670,4875 4755,4875 4762.8,4882.8 D6.1 4785,4900 4795.27,4910.27 CARD1.2 4836.61,4910 4875,4910 4885,4920 4885,4970 4870,4985 4740,4985 4730,4995 R23.1
$1I10\_SPI_CLK: R27.2 RN3.3 | length 300.5
  Top Layer w10: RN3.3 4984.84,5755.16 5000,5740 5000,5650 5040,5610 5040,5580 5047.07,5572.93 5107.41,5572.93 R27.2
$1I10\_SPI_CS: R26.1 RN3.4 U5.1 | length 486.1
  Top Layer w10: v1(4956.83,5673.17) RN3.4 ; v1(5000,5820) U5.1 5066.02,5876.02 5080,5890 5168.26,5890 R26.1
  Bottom Layer w10: v1(4956.83,5673.17) 4993.17,5673.17 5000,5680 v1(5000,5820)
$1I10\_SPI_MISO: RN3.2 U5.2 | length 111.2
  Top Layer w10: RN3.2 5061.18,5774.84 U5.2
$1I10\_SPI_MOSI: RN3.1 U5.5 | length 904.3
  Top Layer w10: RN3.1 4955,5796.36 4955,5910 4980,5935 5370,5935 5424.84,5880.16 5424.84,5680 5414.84,5670 U5.5
$1I10\SD_CARD_DET: RN2.6 U1.84 | length 2083.6
  Top Layer w10: v1(4445,4735) 4335,4735 4300,4770 4300,5200 4335,5235 4975,5235 5025,5285 5025,5605.18 5000.18,5630 4853.7,5630 U1.84 ; v1(4510,4630) 4525.16,4645.16 RN2.6
  Bottom Layer w10: v1(4445,4735) 4445,4660 4475,4630 v1(4510,4630)
$1I10\SDIO_CLK: RN1.5 U1.80 | length 1097.7
  Top Layer w10: v1(4492.5,4847.5) 4515.47,4870.47 RN1.5 ; v1(4720,5550) 4852.44,5550 U1.80
  Bottom Layer w10: v1(4492.5,4847.5) 4495,4850 4495,5155 4515.98,5175.98 4630,5175.98 4700,5245.98 4700,5530 v1(4720,5550)
$1I10\SDIO_CMD: RN1.6 U1.83 | length 1146.1
  Top Layer w10: v1(4470.16,4890.16) RN1.6 ; v1(4705,5610) 4853.39,5610 U1.83
  Bottom Layer w10: v1(4470.16,4890.16) 4470.16,5155.16 4505,5190 4620,5190 4685,5255 4685,5590 v1(4705,5610)
$1I10\SDIO_D0: RN2.8 U1.65 | length 1271.2
  Top Layer w10: RN2.8 4345.47,4684.53 4270,4760 4270,5210 4325,5265 4565,5265 4595,5295 4595,5410.67 U1.65
$1I10\SDIO_D1: RN2.7 U1.66 | length 1291.8
  Top Layer w10: v1(4475,4710) 4340,4710 4284.02,4765.98 4284.02,5204.19 4329.82,5250 4570,5250 4615.34,5295.34 U1.66 ; v1(4500,4660) 4504.84,4664.84 RN2.7
  Bottom Layer w10: v1(4475,4710) 4475,4670 4485,4660 v1(4500,4660)
$1I10\SDIO_D2: RN1.8 U1.78 | length 1208.6
  Top Layer w10: RN1.8 4515.47,4929.53 4495,4950 4495,5155 4525,5185 4974.22,5185 v1(4975,5185.78) ; U1.78 4908.29,5511.71 4965,5455 v1(4975,5455)
  Bottom Layer w10: v1(4975,5185.78) v1(4975,5455)
$1I10\SDIO_D3: RN1.7 U1.79 | length 1229.6
  Top Layer w10: RN1.7 4505.16,4909.84 4480,4935 4480,5160 4510,5190 4510.18,5190 4519.97,5199.79 4934.79,5199.79 v1@4945,5210 ; U1.79 4928.61,5531.39 v1(4950,5510)
  Bottom Layer w10: v1(4950,5210) v1(4950,5510)
$1I10\SPI_CLK: RN3.6 U1.30 | length 982.1
  Top Layer w10: U1.30 4351.04,5866.04 v1(4355,5870) ; v1(4355,5660) v1(4710,5660) ; v1(4910,5660) 4900,5670 4900,5750 4905.16,5755.16 RN3.6
  Bottom Layer w10: v1(4355,5660) v1(4355,5870) ; v1(4710,5660) v1(4910,5660)
$1I10\SPI_CS: RN3.5 U1.29 | length 914
  Top Layer w10: U1.29 4325.73,5885.73 v1(4330,5890) ; v1(4330,5690) v1(4735,5690) ; RN3.5 4925,5733.64 v1(4925,5690)
  Bottom Layer w10: v1(4330,5690) v1(4330,5890) ; v1(4735,5690) v1(4925,5690)
$1I10\SPI_MISO: RN3.7 U1.31 | length 1061.4
  Top Layer w10: U1.31 4383.64,5846.36 4480.77,5749.23 4739.23,5749.23 4749.23,5759.23 4749.23,5913.06 4801.17,5965 4890,5965 4900,5955 4900,5786.32 4911.48,5774.84 RN3.7
$1I10\SPI_MOSI: RN3.8 U1.32 | length 1087.1
  Top Layer w10: U1.32 4378.33,5826.67 4490,5715 4725,5715 v1(4736.24,5726.24) ; RN3.8 4923.17,5953.17 v1(4925,5955)
  Bottom Layer w10: v1(4736.24,5726.24) 4736.24,5921.24 4770,5955 v1(4925,5955)
$1I11\$1N8: LED3.1 R17.1 | length 105.2
  Bottom Layer w10: R17.1 4011.73,7258.61 LED3.1
$1I11\NRST: C37.1 H1.9 R12.1 SW2.3 SW2.4 U1.14 | length 3743.8
  Top Layer w10: v1(4170,6345) v1(4320,6345) 4320,6735 4345,6760 5080,6760 5110,6730 H1.9 ; v1(4495,5790) v1(4587.07,5790) 4587.99,5790.92 4587.99,5917.01 4536.59,5968.41 U1.14
  Bottom Layer w10: SW2.3 3720.36,7232.8 C37.1 3847.9,7272.44 R12.1 3889.64,7230.69 SW2.4 3927.68,7202.32 3935,7195 3935,7155 3950,7140 4155,7140 4170,7125 v1(4170,6345) ; v1(4320,6345) 4320,6120 4430,6010 4430,5810 4450,5790 v1(4495,5790)
$1I11\PB2(BOOT1): LED3.2 R18.2 U1.37 | length 1992.9
  Top Layer w10: v1(4099.49,7205) 4100,7204.49 v1(4100,7095) ; v1(4190,5730) 4191.76,5728.24 U1.37
  Bottom Layer w10: LED3.2 3978.27,7227.07 R18.2 3935,7290 3945,7300 4080,7300 4099.49,7280.51 v1(4099.49,7205) ; v1(4100,7095) 4110,7095 4140,7065 4140,5755 4165,5730 v1(4190,5730)
$1I11\PC0: C38.2 R13.1 SW3.2 U1.15 | length 3236.7
  Top Layer w10: U1.15 4516.91,5963.09 4565,5915 v1(4565,5825)
  Bottom Layer w10: SW3.2 3927.14,6860.34 R13.1 C38.2 4087.44,6762.56 4116.02,6733.98 4116.02,5293.8 4159.82,5250 4600,5250 4625,5275 4625,5810 4610,5825 v1(4565,5825)
$1I11\PC1: C39.2 R14.1 SW4.2 U1.16 | length 2832.1
  Top Layer w10: U1.16 4497.22,5947.78 4535,5910 v1(4535,5855)
  Bottom Layer w10: SW4.2 3932.14,6385.34 R14.1 3990,6317.56 C39.2 4077.44,6312.56 4102.01,6287.99 4102.01,5287.99 4155,5235 4590,5235 4590.98,5235.98 4605.81,5235.98 4639.02,5269.19 4639.02,5815.98 4600,5855 v1(4535,5855)
$1I11\PC2: C40.2 R15.1 SW5.2 U1.17 | length 2405.7
  Top Layer w10: U1.17 4480.33,6003.01 4480.33,5944.85 4505,5920.18 v1(4505,5880)
  Bottom Layer w10: SW5.2 3937.14,5910.34 R15.1 C40.2 4047.44,5832.56 4087.99,5792.01 4087.99,5282.01 4149.02,5220.98 4610.98,5220.98 4655,5265 4655,5820 4595,5880 v1(4505,5880)
$1I11\PC3: C41.2 R16.1 SW6.2 U1.18 | length 2004.4
  Top Layer w10: U1.18 4457.85,5909.22 v1(4460,5907.07)
  Bottom Layer w10: SW6.2 3942.14,5435.34 R16.1 C41.2 4034.05,5367.56 4050,5351.61 4050,5300 4145,5205 4615,5205 4670,5260 4670,5790 4669.02,5790.98 4669.02,5825.81 4595,5899.82 4595,5900 4587.93,5907.07 v1(4460,5907.07)
$1I12\$1N70: C45.2 FPC1.24 | length 389.5
  Top Layer w10: v1(5375,7195) 5375,7067.6 C45.2
  Bottom Layer w10: FPC1.24 5354.72,7250.28 5375,7230 v1(5375,7195)
$1I12\$1N71: C35.2 FPC1.22 | length 250.4
  Top Layer w10: C35.2 5210,7066.96 v1(5210,7110)
  Bottom Layer w10: FPC1.22 5122.01,7152.99 5165,7110 v1(5210,7110)
$1I12\$1N72: C33.2 FPC1.20 | length 206.2
  Top Layer w10: v1(5035,7110) 5035,7064.38 C33.2
  Bottom Layer w10: v1(5035,7110) 5082.64,7157.64 FPC1.20
$1I12\$1N73: C32.2 FPC1.19 | length 253.8
  Top Layer w10: C32.2 4950,7064.38 4950,7110 4990,7150 v1(5025,7150)
  Bottom Layer w10: v1(5025,7150) 5062.96,7187.96 FPC1.19
$1I12\$1N74: C29.2 FPC1.18 | length 310.4
  Top Layer w10: C29.2 4865,7065.19 4865,7110 4940,7185 v1(5025,7185)
  Bottom Layer w10: v1(5025,7185) 5043.27,7203.27 FPC1.18
$1I12\$1N84: C27.2 FPC1.5 | length 197
  Top Layer w10: C27.2 v1(4765,7175)
  Bottom Layer w10: v1(4765,7175) 4787.37,7197.37 FPC1.5
$1I12\$1N85: C25.2 FPC1.4 | length 262.1
  Top Layer w10: C25.2 v1(4680,7195)
  Bottom Layer w10: v1(4680,7195) 4745,7195 4767.68,7217.68 FPC1.4
$1I12\$1N94: C28.2 D4.2 L2.2 Q1.3 | length 684.2
  Top Layer w10: L2.2 4237.01,7145 C28.2 ; D4.2 4340,6910 4352.44,6922.44 C28.2 ; Q1.3 4430,7299.37 4430,7200 4420,7190 4370,7190 4352.44,7172.44 C28.2
$1I12\$1N95: C28.1 D2.2 D3.1 | length 219.7
  Top Layer w10: D2.2 D3.1 4453.37,7131.63 4440,7145 C28.1
$1I12\BS: FPC1.8 R3.2 | length 196.2
  Top Layer w10: v1(4800,7385) 4805.34,7390.34 R3.2
  Bottom Layer w10: v1(4800,7385) 4800,7330 4846.42,7283.58 FPC1.8
$1I12\BUS: FPC1.9 U1.63 | length 5254.6
  Top Layer w10: U1.63 4556.28,5311.28 4524.02,5279.02 4319.19,5279.02 4255.98,5215.81 4255.98,4754.19 4339.66,4670.51 4434.49,4670.51 4570,4535 4570,4430 4669.02,4330.98 4975.81,4330.98 5020,4375.18 v1(5020,5015) ; v1(4866.11,7145) v1(4866.11,7300)
  Bottom Layer w10: v1(4866.11,7145) 4850,7145 4825,7120 4825,6955 5055,6725 5055,6145 5083.73,6116.27 5118.55,6116.27 5215,6019.82 5215,5145 5150,5080 5030,5080 5020,5070 v1(5020,5015) ; FPC1.9 v1(4866.11,7300)
$1I12\CS: FPC1.12 U1.51 | length 2558.1
  Top Layer w10: v1(4220,5410) 4318.74,5410 U1.51
  Bottom Layer w10: v1(4220,5410) 4220,5735 4235,5750 4235,7065 4275,7105 4770,7105 4835,7170 4895,7170 4925.16,7200.16 FPC1.12
$1I12\D/C: FPC1.11 U1.34 | length 2150
  Top Layer w10: v1(4205,5775) 4217.3,5787.3 U1.34
  Bottom Layer w10: v1(4205,5775) 4220,5790 4220,7080 4265,7125 4770,7125 4830.98,7185.98 4881.52,7185.98 4905.48,7209.95 FPC1.11
$1I12\GDR: FPC1.2 Q1.1 R11.2 | length 551.1
  Top Layer w10: Q1.1 4350.63,7380.63 4360.34,7390.34 R11.2 4620.34,7390 4705,7390 4728.31,7366.69 v1(4728.31,7320)
  Bottom Layer w10: FPC1.2 v1(4728.31,7320)
$1I12\PREVGH: C34.2 D4.1 FPC1.21 | length 1306.8
  Top Layer w10: D4.1 4465,6910 4545,6990 4545,7095 4560,7110 4605,7110 4625,7090 4625,6965 4642.07,6947.93 5062.93,6947.93 5085,6970 5085,7060 5092.07,7067.07 5118.12,7067.07 C34.2 5121.21,7108.79 v1(5120,7110)
  Bottom Layer w10: FPC1.21 5102.33,7127.67 v1(5120,7110)
$1I12\PREVGL: C36.2 D3.2 FPC1.23 | length 1206.6
  Top Layer w10: D3.2 4586.63,6953.37 4620,6920 5220,6920 5255,6955 5255,7026.16 C36.2 5295,7066.16 v1(5295,7110)
  Bottom Layer w10: FPC1.23 5140,7248.59 5140,7160 5165,7135 5220,7135 5245,7110 v1(5295,7110)
$1I12\RES: FPC1.10 U1.33 | length 2122.5
  Top Layer w10: v1(4195,5810.29) 4198.3,5806.99 U1.33
  Bottom Layer w10: v1(4195,5810.29) 4195,7085 4260,7150 4772.52,7150 4822.52,7200 4875,7200 4885.79,7210.79 FPC1.10
$1I12\RESE: FPC1.3 Q1.2 R4.1 | length 1280.8
  Top Layer w10: Q1.2 4310,7303.23 4310,7400 4332.07,7422.07 5007.93,7422.07 5020,7410 R4.1 5020,7360 5010,7350 4788,7350 v1(4776.64,7338.64)
  Bottom Layer w10: FPC1.3 4750,7252.31 4750,7312 v1(4776.64,7338.64)
$1I12\SCK: FPC1.13 U1.52 | length 3156.6
  Top Layer w10: v1(4315,5320) 4339.74,5344.74 U1.52 ; v1(4760,6885) v1(4944.85,6885)
  Bottom Layer w10: v1(4315,5320) 4260,5320 4250,5330 4250,7050 4285,7085 4745,7085 4760,7070 v1(4760,6885) ; v1(4944.85,6885) FPC1.13
$1I12\SDA: FPC1.14 U1.54 | length 3211.5
  Top Layer w10: v1(4379.11,5350) U1.54 ; v1(4725,6850) v1(4995,6850)
  Bottom Layer w10: v1(4379.11,5350) 4295,5350 4265,5380 4265,7045 4290,7070 4700,7070 4725,7045 v1(4725,6850) ; FPC1.14 4964.53,6925.47 4995,6895 v1(4995,6850)
$1I13\$1N65: R6.1 USB1.B5 | length 251.8
  Top Layer w10: USB1.B5 3947.48,4172.52 3955,4165 3955,4080 3975,4060 R6.1
$1I13\$1N66: R7.1 USB1.A5 | length 221.8
  Top Layer w10: USB1.A5 3953.11,4211.89 3980,4185 3980,4140 4000,4120 4055.34,4120 R7.1
$1I13\$1N69: R5.2 U4.2 | length 109.8
  Top Layer w10: R5.2@4210,4240.34 4213.85,4236.49 U4.2
$1I13\$1N73: LED1.1 R8.2 | length 76.9
  Top Layer w10: R8.2 LED1.1
$1I13\$1N74: LED2.2 R9.2 | length 80.8
  Top Layer w10: R9.2 LED2.2
$1I13\$1N75: LED1.2 U4.6 | length 450.3
  Top Layer w10: LED1.2 4660,4065 4670,4075 4670,4220 4660,4230 4595,4230 4585,4220 4585,4195 4576.49,4186.49 U4.6
$1I13\$1N76: LED2.1 U4.7 | length 538.4
  Top Layer w10: LED2.1 4665,3995 4685,4015 4685,4235 4670,4250 4585,4250 4571.49,4236.49 U4.7
$1I13\NET_BAT: C26.2 Q2.3 U2.1 U4.5 | length 1550.2
  Top Layer w10: Q2.3 4015,4510 3955,4450 3955,4350 3970,4335 4350,4335 4365,4320 4365,4140 4375,4130 4540.74,4130 U4.5 4624.05,4136.49 C26.2 v1(4625,4095)
  Bottom Layer w10: v1(4625,4095) 4625,4055 4645,4035 U2.1
$1I13\VIN_RAM: D1.2 Q2.2 SW1.2 | length 954.2
  Top Layer w10: SW1.2 3706.81,4625 3686.81,4605 3686.81,4418.19 3705.61,4399.39 v1(3785,4399.39) ; v1(4050,4500) 4050,4543.23 Q2.2 4052.4,4708.12 D1.2
  Bottom Layer w10: v1(3785,4399.39) 3829.39,4399.39 3840,4410 3840,4490 3850,4500 v1(4050,4500)
$1I13\VOUT_RAM: C19.2 C20.2 LDO1.1 LDO1.3 SW1.3 | length 910.2
  Top Layer w10: SW1.3 3816.26,4546.26 3830,4560 3830,4770 3850,4790 4055,4790 4075.42,4810.42 LDO1.1 ; C20.2 4155.04,4842.6 LDO1.1 ; C19.2 4078.02,4920 LDO1.3 4032.4,4917.4 4025,4910 4025,4855 4037.4,4842.6 LDO1.1
+3V3: C7.1 C12.2 C13.2 C14.2 C15.2 C16.2 C17.2 C18.2 C21.2 C22.2 C30.2 C31.2 C42.1 C43.2 C44.1 CARD1.4 FPC1.15 FPC1.16 H1.2 L1.1 L2.1 LDO1.5 R1.1 R12.2 R13.2 R14.2 R15.2 R16.2 R19.2 R20.2 R21.2 R22.2 R23.2 R24.2 R26.2 TP1.1 U1.6 U1.11 U1.28 U1.50 U1.75 U1.100 U5.3 U5.7 U5.8 | length 12936
  Top Layer w10: C22.2 C21.2 C18.2 C17.2 C16.2 C15.2 C14.2 C13.2 C12.2 3931.7,5529.14 TP1.1 ; TP1.1@3936.7,5539.65 3960.19,5563.14 4111.18,5563.14 4118.25,5570.21 4118.25,5660.55 R1.1 4148,5690.31 C7.1 4148,5830.21 4171.18,5830.21 4178.25,5837.29 4178.25,5885.21 4198.25,5905.21 4258.84,5905.21 U1.28 4259.45,5905 4288.41,5905 4313.41,5930 4380,5930 4405,5905 4405,5845 4485,5765 4620,5765 4642.07,5787.07 4642.07,5935 4620,5935 4595.65,5959.35 U1.11 ; v1(4065,5500) 4065,5473.35 4066.01,5472.34 4066.53,5471.83 ; U1.50@4258.52,5471.83 U1.50 ; v1(4625,5150) 4617.93,5157.07 4534.51,5157.07 4527.44,5150 C43.2 C42.1 4533.56,5040 4562.26,5068.7 4618.7,5068.7 4659.66,5109.66 R22.2 R23.2 R19.2 4820.34,5109.66 4915,5015 4915,4826.3 ; 4645,5935 4670,5935 4695,5960 4695,6004.88 U1.6 4696.87,6008.59 4696.87,6038.39 4708.48,6050 v1(4980,6050) 4980,6270 H1.2 4950,6360 4950,6435 4965,6450 5125,6450 5155,6480 5155,6765 5180,6790 5395,6790 5415,6810 5415,7285 5395,7305 v1(5003.9,7305) ; v1(4775,5505) 4792.5,5487.5 U1.75 4792.5,5369.57 v1(4795,5367.07) ; v1(4775,5635) 4775,5880 v1(4780,5885) 4780,5920 4805,5945 4853.3,5945 U1.100 ; R20.2 4799.66,4520.94 4803.99,4525.27 ; CARD1.4 4912.36,4823.66 4915,4826.3 ; R21.2 4930,4485.34 4930,4515 4920,4525 4804.27,4525 4803.99,4525.27 ; U5.3 5139.08,5720 ; v1(5140,5760) 5139.08,5759.08 5139.08,5720 ; R26.2 5309.5,5895.5 5343.98,5861.02 U5.8 ; C44.1 5327.56,5527.56 5315,5515 5155,5515 5140,5530 5140,5719.08 5139.08,5720 ; U5.7 5250,5770 5200,5720 5139.08,5720 ; U5.7@5348.98,5765 U5.8@5348.98,5815 ; 4803.99,4525.27 4679.66,4525.27 4669.66,4515.27 R24.2 4665,4480.34 4665,4360 4680,4345 4970,4345 5005,4380 5005,4670 4915,4760 4915,4826.3
  Top Layer w15: C22.2 3967.18,4860 LDO1.5 ; C12.2 3880.22,5472.34 4066.01,5472.34 ; 4066.53,5471.83 U1.50@4258.52,5471.83
  Top Layer w20: C31.2 C30.2 3872.8,6905 3877.56,6909.76 ; v1(3850,7450) 3837.99,7437.99 L2.1 3877.56,7130.43 3877.56,6918.33 ; C12.2 3877.56,5972.16 ; v1(3930,6920) 3879.23,6920 3877.56,6918.33 ; v1(3935,5969.66) 3880.06,5969.66 3877.56,5972.16 ; v1(3935,6444.66) 3933.92,6445.74 3877.56,6445.74 ; 3877.56,5972.16 3877.56,6445.74 ; 3877.56,6445.74 3877.56,6909.76 ; 3877.56,6909.76 3877.56,6918.33
  Bottom Layer w10: v1(4625,5150) 4715,5240 4715,5340 4737.07,5362.07 4790,5362.07 v1(4795,5367.07) ; v1(4775,5505) v1(4775,5635) ; v1(4780,5885) 5138.94,5885 5140,5886.06 ; v1(4980,6050) 5105,6050 5140,6015 5140,5886.06 ; FPC1.16 v1(5003.9,7305) ; v1(5140,5760) 5140,5886.06
  Bottom Layer w15: R16.2 4000.34,5500 v1(4065,5500) ; FPC1.15 FPC1.16
  Bottom Layer w20: R12.2 v1(3850,7450) ; v1(3930,6920) 3989.66,6920 R13.2 ; v1(3935,5969.66) R15.2 ; v1(3935,6444.66) R14.2
AGND: C5.1 C6.2 C10.2 C11.1 R2.2 TP3.1 U1.20 | length 932.7
  Top Layer w10: R2.2 4150.1,5956.47 C10.2 C11.1 4148.25,6030.46 TP3.1 4148.25,6245.21 4168.25,6265.21 4218.25,6265.21 4235.69,6247.77 C6.2 C5.1 ; C5.1 4235.75,6092.71 4248.25,6080.21 4278.25,6080.21 4303.17,6055.29 4303.17,5973.21 4313.06,5963.32 4405.79,5963.32 4418.48,5976 U1.20
GND: C1.1 C2.1 C3.1 C4.1 C7.2 C8.1 C9.1 C12.1 C13.1 C14.1 C15.1 C16.1 C17.1 C18.1 C19.1 C20.1 C21.1 C22.1 C23.1 C24.2 C25.1 C26.1 C27.1 C29.1 C30.1 C31.1 C32.1 C33.1 C34.1 C35.1 C36.1 C37.2 C38.1 C39.1 C40.1 C41.1 C42.2 C43.1 C44.2 C45.1 CARD1.6 CARD1.10 CARD1.11 CARD1.12 CARD1.13 D2.1 D5.2 D6.2 D7.2 D8.2 D9.2 D10.2 D11.2 FPC1.17 FPC1.25 FPC1.26 H1.4 H1.6 LDO1.2 R2.1 R3.1 R4.2 R5.1 R6.2 R7.2 R10.2 R11.1 R17.2 R18.1 SW2.1 SW2.2 SW3.1 SW4.1 SW5.1 SW6.1 U1.10 U1.27 U1.74 U1.99 U2.2 U4.3 U4.9 U5.4 USB1.7 USB1.A12 USB1.B12 X1.2 X1.4 | length 20511.8
  Top Layer w10: v1(3707.93,7160) v1(3707.93,7325.49) ; v1(3710,5165) 3819.11,5165 C16.1 ; USB1.7@3745.54,4022.13 3895.15,4022.13 3904.99,4031.97 USB1.A12 ; C12.1 C13.1 C14.1 C15.1 C16.1 ; v1(3860,4815) 3822.44,4852.56 C22.1 C21.1 C18.1 C17.1 C16.1 ; v1(3895,4575) 3900,4570 R10.2 ; USB1.7@3895.15,4362.28 3904.99,4352.44 USB1.B12 4019.06,4298.5 C24.2 C23.1 4192.9,4277.56 R5.1 4210.34,4295 v1(4265,4295) ; v1(4000,5055) 4155,5055 4190,5090 4190,5412.52 4231.29,5453.8 4398.8,5453.8 v1(4520,5575) ; v1(4040,5595) 4065.21,5620.21 C9.1 ; v1(4040,5765) 4088.1,5765 C7.2 4105.21,5760.21 4120,5775 4120,5880 4109.13,5890.87 R2.1 4089.91,5890 v1(4045,5890) ; LDO1.2 4077.42,4882 4212.56,4882 ; R6.2 R7.2 4120,4125.34 v1(4120,4170) ; C19.1 4212.56,4882 ; v1(4215,4755) 4215,4842.56 C20.1 4212.56,4882 ; U1.27 4224.9,5925.1 4200,5950 4200,5990 4215,6005 4251.56,6005 4312.55,5944.02 4385.81,5944.02 4419.02,5910.81 4419.02,5850.98 4450,5820 v1(4520,5820) ; v1(4265,4200) 4304.71,4200 U4.3 ; C2.1 4425.69,6260.69 4443.68,6278.68 X1.4 4521.26,6320 4600,6320 4610,6310 4610,6210 ; X1.2 4568.31,6210 4610,6210 ; v1(4580,4985) 4580,5037.44 C42.2 ; C43.1 v1(4620,5110) 4660.78,5150.78 4859.61,5150.78 CARD1.12 4935.39,5075 4957.89,5075 ; C26.1 4592.44,4160 4484.21,4160 U4.9 4435,4213.76 v1(4435,4370) 4595,4370 4690,4275 v1(4770,4275) ; v2(4640,5960) 4625,5960 4615,5970 4615,6005.46 U1.10 4615.34,6120.68 C1.1 ; C4.1 C1.1 ; v1(4710,4595) 4732.2,4595 D5.2 ; v1(4710,4650) D8.2 ; v1(4710,4700) D9.2 4735,4702.2 4735,4730 4742.05,4737.05 CARD1.6 ; v1(4710,4780) D11.2 ; v1(4710,4850) D10.2 ; v1(4710,4900) D6.2 ; v1(4710,4950) D7.2 ; v1(4770,4400) v1(4940,4400) ; U1.74 v2(4772.82,5450) ; C8.1 4830,5344.41 v1(4830,5370) ; v2(4807.34,5908.02) 4807.34,5917.44 4815,5925.1 U1.99 ; v1(4815,4559.88) CARD1.10 ; C3.1 4865.81,6251.46 4847.61,6269.66 4819.33,6269.66 4794,6295 4684.63,6295 4665.23,6275.61 4665.23,6220.23 4655,6210 4610,6210 ; v1(4890,5400) v1(5000,5400) ; v1(4960,5010) 4960,5072.89 4957.89,5075 ; R4.2 5020.34,7450 5110,7450 5120,7440 v1(5120,7410) ; v1(5066.02,5485) 5340,5485 5355,5500 5355,5610 5335,5630 5290,5630 5272.44,5612.44 C44.2 ; v1(5066.02,5625) U5.4 ; v1(5250,4455) 5250,4556.22 CARD1.11 ; CARD1.13 5253.66,5113.66 5215,5075 4957.89,5075 ; 4610,6210 4610,6168.31 4610.81,6167.5 C1.1
  Top Layer w20: v1(4506.77,6060.21) v1(4476.07,6060.21) 4445.89,6060.21 v1(4439.98,6066.12) 4431.71,6074.39 v1(4398.12,6074.39) v1(4378.76,6093.76) v1(4356.26,6116.26) 4356.26,6138.74 v1(4355,6140) v1(4355,6170) v1(4355,6200) 4375,6220 v1(4375,6225) 4383.25,6233.25 v1(4383.25,6251.45) v1(4383.25,6279.64) 4395,6291.39 v1(4395,6305) 4396.82,6305 v1(4417.64,6325.82) v1(4435.54,6343.72) 4471.71,6343.72 v1(4475,6347.01) v1(4505,6347.01) v1(4545,6347.01) v1(4580,6347.01) 4617.99,6347.01 v1(4620,6345) 4650,6345 v1(4655,6340) 4680,6340 v1(4685,6335) v1(4725,6335) v1(4755,6335) v1(4795,6335) 4825,6335 v1(4830,6330) 4838.06,6330 v1(4853.25,6314.81) 4855.19,6314.81 v1(4880,6290) 4893.25,6276.75 v1(4893.25,6257.71) 4902.8,6248.16 v1(4902.8,6220.66) 4910,6213.46 v1(4910,6185) v1(4910,6145) v1(4910,6110) 4910,6085 v1(4905,6080) 4900,6075 v1(4875,6075) 4822.01,6075 v1(4820,6072.99)
  Bottom Layer w10: v1(3707.93,7160) 3707.93,7130.1 SW2.1 ; v1(3707.93,7325.49) 3710,7327.56 C37.2 3802.44,7327.56 3830,7300 3910,7300 3935,7325 R18.1 R17.2 ; v1(3710,5165) 3710,5225 3732.52,5247.52 SW6.1 ; USB1.7@3745.54,4022.13 3745.54,4362.28 3895.15,4362.28 4072.28,4362.28 4120,4410 4120,4505 4050,4575 v1(3895,4575) 3895,4780 v1(3860,4815) 4155,4815 v1(4215,4755) ; SW2.2 SW2.1 ; C39.1 3915.08,6187.52 SW4.1 3811.36,6191.16 3710,6191.16 ; C38.1 3940.08,6657.52 SW3.1 3811.13,6653.65 3710,6653.65 ; v1(4000,5055) 4000,5307.44 C41.1 3930.08,5247.52 SW6.1 ; v1(4040,5595) v1(4040,5765) 4002.44,5765 C40.1 3930.08,5717.52 SW5.1 3813.84,5716.36 3710,5716.36 ; v1(4045,5890) v1(4045,6250) ; v1(4120,4170) 4120,4185 4135,4200 v1(4265,4200) v1(4265,4295) 4265,4365 4285,4385 4420,4385 v1(4435,4370) ; v1(4520,5575) v1(4520,5820) ; v1(4620,5110) 4620,5095 4580,5055 v1(4580,4985) 4615,4950 v1(4710,4950) v1(4710,4900) v1(4710,4850) v1(4710,4780) v1(4710,4700) v1(4710,4650) v1(4710,4595) 4710,4570 4720.12,4559.88 v1(4815,4559.88) ; v2(4640,5960) 4695,5960 4715,5980 4965,5980 4980,5965 4980,5935 4953.02,5908.02 v2(4807.34,5908.02) ; v1(4770,4275) v1(4770,4400) ; v2(4772.82,5450) 4800,5450 4830,5420 v1(4830,5370) ; v1(4890,5400) 4860,5370 v1(4830,5370) ; v1(4940,4400) v1(4770,4400) ; v1(4960,5010) 4925,5010 4830,5105 v1(4830,5370) ; v1(5000,5400) 5045,5400 5066.02,5421.02 v1(5066.02,5485) v1(5066.02,5625) ; FPC1.17 5023.59,7288.59 5084.72,7349.72 FPC1.25 5236.18,7398.82 5225,7410 v1(5120,7410) ; v1(5250,4455) 5145.12,4559.88 v1(4815,4559.88) ; 3710,5716.36 3710,5352.52 SW6.1 ; 3710,5716.36 3710,6191.16 ; 3710,6191.16 3710,6653.65 ; 3710,6653.65 3710,7107.32 SW2.1 ; v1(4770,4400) 4815,4445 v1(4815,4559.88)
  other v1: 4055,5105 4100,5105 4055,5160 4100,5160 5100,5970 5030,5980 5075,6000 4985,6010 4925,6015 4845,6020 4945,6075
VBUS_5V: C23.2 C24.1 D1.1 H1.7 Q2.1 R8.1 R9.1 R10.1 U4.4 USB1.A9 USB1.B9 | length 5606.6
  Top Layer w10: D1.1 3895,4719.28 3895,4620 3905,4610 3950,4610 3977.6,4582.4 Q2.1 3977.6,4497.6 3955.34,4475.34 R10.1 ; U4.4 4325.34,4129.37 R8.1 R9.1
  Top Layer w20: R10.1 3894.66,4470 3845,4470 3835,4460 3835,4255.53 ; USB1.A9 3861.85,4133.15 3835,4160 3835,4255.53 ; v1(4240,4020) 4240,4136.49 4243.51,4136.49 ; U4.4 4243.51,4136.49 ; 3835,4255.53 3839.27,4251.26 USB1.B9 3958.74,4251.26 3990,4220 4037.56,4220 C24.1 C23.2 4157.56,4222.44 4243.51,4136.49
  Bottom Layer w20: v1(4240,4020) 4240,4155 4255,4170 5365,4170 5410,4215 5410,6550 5360,6600 H1.7
pads on no net: FPC1.1 FPC1.6 FPC1.7 LDO1.4 RN2.4 RN2.5 SW1.1 SW1.4 SW1.5 U1.1 U1.2 U1.3 U1.4 U1.5 U1.7 U1.23 U1.24 U1.25 U1.26 U1.35 U1.36 U1.38 U1.39 U1.40 U1.41 U1.42 U1.43 U1.44 U1.45 U1.46 U1.47 U1.48 U1.53 U1.55 U1.56 U1.57 U1.58 U1.59 U1.60 U1.61 U1.62 U1.64 U1.67 U1.70 U1.71 U1.77 U1.81 U1.82 U1.85 U1.86 U1.87 U1.88 U1.90 U1.91 U1.92 U1.93 U1.95 U1.96 U1.97 U1.98 U4.1 U4.8

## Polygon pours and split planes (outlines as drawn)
GND on Top Layer (solid, remove dead copper, pour order 0): 3405,7945 6335,7945 6335,3525 3405,3525
GND on Bottom Layer (solid, remove dead copper, pour order 4): 3000,8145 7025,8145 7025,3000 3000,3000

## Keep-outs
Board Outline Layer:
  region: 4393.25,6060.21 4353.25,6100.21 4353.25,6210.21 4383.25,6240.21 4383.25,6291.43 4452.03,6360.21 4633.25,6360.21 4668.25,6325.21 4853.25,6325.21 4893.25,6285.21 4893.25,6230.21 4928.25,6195.21 4928.25,6080.21 4908.25,6060.21
  lines w10: 3670,4059.8 ccw(c3788.11,4059.8) 3788.11,3941.69 5323.54,3941.69 ccw(c5323.54,4059.8) 5441.65,4059.8 5441.65,7366.89 ccw(c5323.54,7366.89) 5323.54,7485 3788.11,7485 ccw(c3788.11,7366.89) 3670,7366.89 3670,4059.8

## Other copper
Top Layer:
  drawing of 576 lines, arcs and shapes, not listed
Bottom Layer:
  drawing of 246 lines, arcs and shapes, not listed

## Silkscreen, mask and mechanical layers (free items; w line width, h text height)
Top Silkscreen Layer:
  drawing of 46 lines, arcs and shapes, not listed
  text "TX" at 4785,6695 h45
  text "RST" at 4870,6690 h45
  text "RX" at 4785,6590 h45
  text "5V" at 4885,6590 h45
  text "GND" at 4775,6480 h45
  text "DIO" at 4880,6480 h45
  text "GND" at 4785,6375 h45
  text "CLK" at 4880,6375 h45
  text "3V3" at 4960,6215 h45
  text "SWO" at 5070,6215 h45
